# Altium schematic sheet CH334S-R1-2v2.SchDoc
size 209 x 148 mm; PageSetup: Record=PageOptions¦CenterHorizontal=True¦CenterVertical=True¦PrintScale=0.65¦XCorrection=1.00¦YCorrection=1.00¦PrintKind=1¦BorderSize=5000000¦LeftOffset=0¦BottomOffset=0¦Orientation=2¦PaperLength=1000¦PaperWidth=1000¦Scale=100¦PaperSource=7¦PrintQuality=-4¦MediaType=1¦DitherType=10¦PaperKind=16 开 195x270¦PrintScaleMode=1
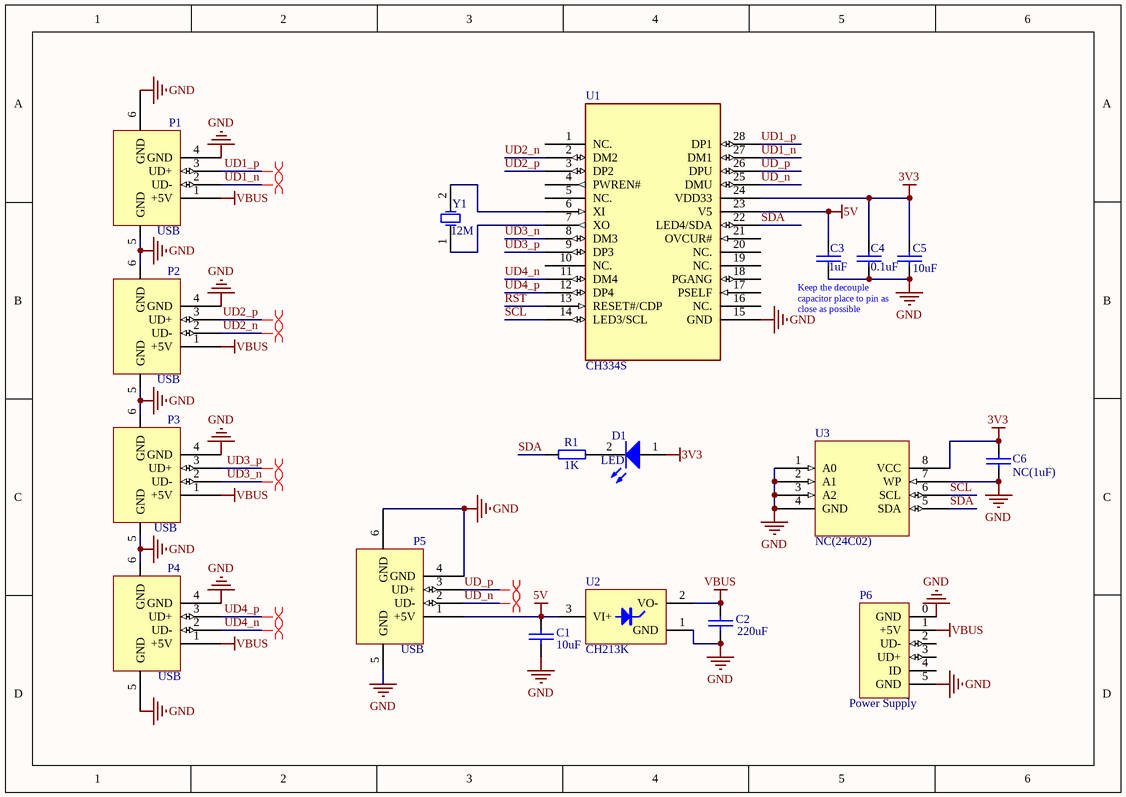
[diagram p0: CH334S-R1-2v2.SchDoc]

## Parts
C1  10uF  [0603_C]
C2  220uF  [CD0.1]
C3  1uF  [0603_C]
C4  0.1uF  [0603_C]
C5  10uF  [0603_C]
C6  NC(1uF)  [0603_C]
D1  LED  [0603+]
P1  USB  [USBAF]
P2  USB  [USB2.0-A-F-TH_4P-V_13.7mm]
P3  USB  [USB2.0-A-F-TH_4P-V_13.7mm]
P4  USB  [USB2.0-A-F-TH_4P-V_13.7mm]
P5  USB  [USBAF]
P6  Power Supply  [USBMICROB-02-GXPX-A1T2]
R1  1K  [0603_R]
U1  CH334S  [SSOP28]
U2  CH213K  [SOT-23-3]
U3  NC(24C02)  [SOIC-8_150mil]
Y1  12M  [XT_AT49]

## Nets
3V3: C4.1 C5.1 C6.2 D1.1(A) U1.24(VDD33) U3.8(VCC)
5V: C1.1 C3.1 P5.1(+5V) U1.23(V5) U2.3(VI+)
GND: C1.2 C2.2 C3.2 C4.2 C5.2 C6.1 P1.4(GND) P1.5(GND) P1.6(GND) P2.4(GND) P2.5(GND) P2.6(GND) P3.4(GND) P3.5(GND) P3.6(GND) P4.4(GND) P4.5(GND) P4.6(GND) P5.4(GND) P5.5(GND) P5.6(GND) P6.0(GND) P6.5(GND) U1.15(GND) U2.1(GND) U3.1(A0) U3.2(A1) U3.3(A2) U3.4(GND) U3.7(WP)
VBUS: C2.1 P1.1(+5V) P2.1(+5V) P3.1(+5V) P4.1(+5V) P6.1(+5V) U2.2(VO-)
RST: U1.13(RESET#/CDP)
SCL: U1.14(LED3/SCL) U3.6(SCL)
SDA: R1.1 U1.22(LED4/SDA) U3.5(SDA)
UD1_n: P1.2(UD-) U1.27(DM1)
UD1_p: P1.3(UD+) U1.28(DP1)
UD2_n: P2.2(UD-) U1.2(DM2)
UD2_p: P2.3(UD+) U1.3(DP2)
UD3_n: P3.2(UD-) U1.8(DM3)
UD3_p: P3.3(UD+) U1.9(DP3)
UD4_n: P4.2(UD-) U1.11(DM4)
UD4_p: P4.3(UD+) U1.12(DP4)
UD_n: P5.2(UD-) U1.25(DMU)
UD_p: P5.3(UD+) U1.26(DPU)
NetD1_2: D1.2(K) R1.2
NetU1_6: U1.6(XI) Y1.2(OSC2)
NetU1_7: U1.7(XO) Y1.1(OSC1)

Not connected (* = marked no-connect by the designer): P6 2(UD-) 3(UD+) 4(ID); U1 1(NC.) 4(PWREN#) 5(NC.) 10(NC.) 16(NC.) 17(PSELF) 18(PGANG) 19(NC.) 20(NC.) 21(OVCUR#)

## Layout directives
differential pair: UD1_n, UD1_p, UD2_n, UD2_p, UD3_n, UD3_p, UD4_n, UD4_p, UD_n, UD_p

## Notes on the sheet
- Keep the decouple capacitor place to pin as close as possible

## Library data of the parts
C1-C6 = CAP: Capacitor
D1 = LED: Typical INFRARED GaAs LED
P1-P5 = USB: USB Port
P6 = MicroUSB: MicroUSB Port
R1 = RES
U1 = CH334S: 4 ports High-Speed USB MTT Hub with over current detect & power control
U2 = CH213K: Ideal Diode 5V*1A
U3 = 24C01
Y1 = XTAL: Crystal Oscillator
